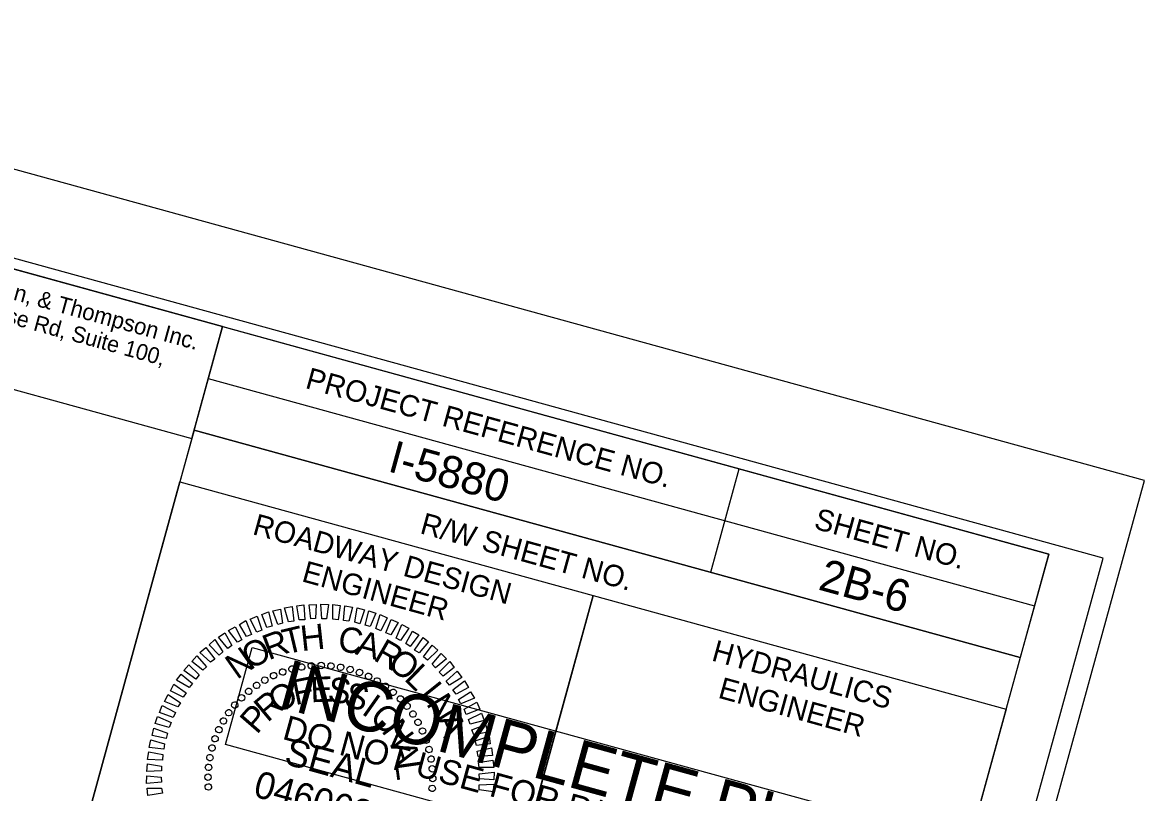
# Model space of a CAD drawing. Extents: x 1641192 to 2864602, y 841295 to 973236.
# Drawn here: x 1642843.9 to 1643105.8, y 842278.3 to 842457.9 of the extents above; entities that cross this region are included whole.
import ezdxf

# ---------------------------------------------------------------- set-up
doc = ezdxf.new("R2010")
doc.units = 0
for name, color, linetype in [('Old_Level_2', 7, 'Continuous'), ('Prop Dimension Text', 7, 'Continuous'), ('Sheet Data Field CELL', 7, 'Continuous'), ('Sheet Plan CELL', 7, 'Continuous'), ('Sheet Plot Border Inside CELL', 7, 'Continuous'), ('Sheet Plot Border Outside CELL', 7, 'Continuous'), ('Sheet Sticker Incomplete CELL', 7, 'Continuous')]:
    doc.layers.add(name, color=color, linetype=linetype)

msp = doc.modelspace()

# ---------------------------------------------------------------- linework, layer by layer
at = {"layer": 'Old_Level_2'}
for p, q in [((1642906.8, 842307.08), (1642906.8, 842307.08)), ((1642909.03, 842307.58), (1642909.03, 842307.58)), ((1642911.27, 842307.87), (1642911.27, 842307.87)), ((1642913.55, 842307.94), (1642913.55, 842307.94)), ((1642915.88, 842307.77), (1642915.88, 842307.77)), ((1642918.14, 842307.52), (1642918.14, 842307.52)), ((1642920.38, 842306.99), (1642920.38, 842306.99)), ((1642900.41, 842304.5), (1642900.41, 842304.5)), ((1642902.48, 842305.59), (1642902.48, 842305.59)), ((1642904.57, 842306.41), (1642904.57, 842306.41)), ((1642922.57, 842306.27), (1642922.57, 842306.27)), ((1642924.66, 842305.36), (1642924.66, 842305.36)), ((1642926.67, 842304.36), (1642926.67, 842304.36)), ((1642896.67, 842301.9), (1642896.67, 842301.9)), ((1642898.49, 842303.32), (1642898.49, 842303.32)), ((1642928.61, 842303.1), (1642928.61, 842303.1)), ((1642930.4, 842301.67), (1642930.4, 842301.67)), ((1642894.94, 842300.4), (1642894.94, 842300.4)), ((1642932.12, 842300.15), (1642932.12, 842300.15)), ((1642891.99, 842296.9), (1642891.99, 842296.9)), ((1642893.42, 842298.69), (1642893.42, 842298.69)), ((1642933.62, 842298.42), (1642933.62, 842298.42)), ((1642935.04, 842296.59), (1642935.04, 842296.59)), ((1642890.73, 842294.95), (1642890.73, 842294.95)), ((1642936.22, 842294.67), (1642936.22, 842294.67)), ((1642889.73, 842292.94), (1642889.73, 842292.94)), ((1642937.31, 842292.61), (1642937.31, 842292.61)), ((1642888.09, 842288.66), (1642888.09, 842288.66)), ((1642888.82, 842290.85), (1642888.82, 842290.85)), ((1642938.12, 842290.51), (1642938.12, 842290.51)), ((1642938.79, 842288.29), (1642938.79, 842288.29)), ((1642887.57, 842286.42), (1642887.57, 842286.42)), ((1642939.3, 842286.05), (1642939.3, 842286.05)), ((1642887.32, 842284.17), (1642887.32, 842284.17)), ((1642939.59, 842283.82), (1642939.59, 842283.82)), ((1642887.15, 842281.83), (1642887.15, 842281.83)), ((1642913.4, 842281.69), (1642913.4, 842281.69)), ((1642939.65, 842281.54), (1642939.65, 842281.54)), ((1642887.21, 842279.55), (1642887.21, 842279.55)), ((1642939.49, 842279.21), (1642939.49, 842279.21))]:
    msp.add_line(p, q, dxfattribs=at)
for points in [[(1642900.91, 842316.74), (1642899.7, 842319.8), (1642901.26, 842320.43), (1642902.18, 842317.06)], [(1642903.46, 842317.43), (1642902.29, 842320.65), (1642904.07, 842321.06), (1642904.58, 842317.79)], [(1642905.95, 842318.09), (1642905.06, 842321.34), (1642906.81, 842321.65), (1642907.18, 842318.26)], [(1642908.45, 842318.58), (1642907.89, 842321.86), (1642909.56, 842322.08), (1642909.8, 842318.56)], [(1642911.14, 842318.76), (1642910.76, 842322.09), (1642912.44, 842322.15), (1642912.3, 842318.84)], [(1642913.74, 842318.79), (1642913.5, 842322.25), (1642915.31, 842322.17), (1642914.87, 842318.77)], [(1642916.32, 842318.72), (1642916.34, 842322.17), (1642918.05, 842321.9), (1642917.57, 842318.56)], [(1642918.83, 842318.4), (1642919.1, 842321.79), (1642920.87, 842321.55), (1642920.08, 842318.24)], [(1642921.42, 842318.01), (1642922.01, 842321.37), (1642923.67, 842320.89), (1642922.63, 842317.65)], [(1642923.84, 842317.33), (1642924.69, 842320.63), (1642926.34, 842320.15), (1642925.04, 842316.97)], [(1642926.33, 842316.53), (1642927.38, 842319.77), (1642928.97, 842319.04), (1642927.5, 842316.02)], [(1642896.16, 842314.66), (1642894.51, 842317.46), (1642896.04, 842318.37), (1642897.31, 842315.12)], [(1642898.59, 842315.71), (1642897.04, 842318.7), (1642898.68, 842319.42), (1642899.72, 842316.12)], [(1642928.66, 842315.5), (1642929.95, 842318.63), (1642931.56, 842317.95), (1642929.84, 842315.04)], [(1642931.1, 842314.28), (1642932.45, 842317.45), (1642934.07, 842316.6), (1642932.1, 842313.76)], [(1642891.77, 842311.85), (1642889.65, 842314.5), (1642891.1, 842315.53), (1642892.72, 842312.58)], [(1642894.04, 842313.32), (1642891.99, 842316.06), (1642893.55, 842316.9), (1642895.06, 842313.92)], [(1642933.36, 842313), (1642934.93, 842315.95), (1642936.37, 842315.04), (1642934.34, 842312.37)], [(1642887.72, 842308.68), (1642885.27, 842310.92), (1642886.65, 842312.08), (1642888.76, 842309.38)], [(1642889.76, 842310.31), (1642887.47, 842312.74), (1642888.8, 842313.96), (1642890.66, 842311.11)], [(1642935.41, 842311.51), (1642937.39, 842314.4), (1642938.65, 842313.43), (1642936.48, 842310.85)], [(1642937.44, 842309.96), (1642939.47, 842312.62), (1642940.86, 842311.51), (1642938.41, 842309.12)], [(1642885.95, 842306.81), (1642883.38, 842308.82), (1642884.55, 842310.19), (1642886.8, 842307.62)], [(1642939.47, 842308.2), (1642941.58, 842310.73), (1642942.88, 842309.48), (1642940.28, 842307.34)], [(1642884.34, 842304.74), (1642881.49, 842306.71), (1642882.66, 842308.09), (1642885.13, 842305.73)], [(1642941.1, 842306.32), (1642943.62, 842308.8), (1642944.67, 842307.4), (1642942.06, 842305.43)], [(1642882.75, 842302.77), (1642879.84, 842304.49), (1642880.91, 842305.89), (1642883.58, 842303.69)], [(1642942.78, 842304.27), (1642945.37, 842306.57), (1642946.4, 842305.12), (1642943.56, 842303.31)], [(1642944.31, 842302.21), (1642947.06, 842304.31), (1642947.96, 842302.78), (1642945.07, 842301.2)], [(1642881.37, 842300.54), (1642878.4, 842302), (1642879.18, 842303.58), (1642882.05, 842301.5)], [(1642945.67, 842299.97), (1642948.46, 842301.79), (1642949.37, 842300.26), (1642946.23, 842298.96)], [(1642880.09, 842298.27), (1642877.05, 842299.48), (1642877.85, 842301.12), (1642880.76, 842299.23)], [(1642946.98, 842297.69), (1642949.89, 842299.37), (1642950.61, 842297.73), (1642947.43, 842296.49)], [(1642879.02, 842295.8), (1642875.85, 842296.93), (1642876.5, 842298.6), (1642879.58, 842296.95)], [(1642947.99, 842295.32), (1642951.02, 842296.81), (1642951.61, 842295.1), (1642948.35, 842294.2)], [(1642878.14, 842293.43), (1642874.87, 842294.37), (1642875.4, 842296.02), (1642878.55, 842294.62)], [(1642948.78, 842292.91), (1642951.95, 842294.14), (1642952.53, 842292.38), (1642949.23, 842291.71)], [(1642877.44, 842290.91), (1642874.11, 842291.6), (1642874.55, 842293.32), (1642877.75, 842292.12)], [(1642949.52, 842290.34), (1642952.81, 842291.39), (1642953.07, 842289.65), (1642949.88, 842289.22)], [(1642876.84, 842288.36), (1642873.45, 842288.8), (1642873.79, 842290.55), (1642877.05, 842289.61)], [(1642949.98, 842287.9), (1642953.35, 842288.66), (1642953.6, 842286.87), (1642950.2, 842286.66)], [(1642876.52, 842285.85), (1642873.05, 842285.99), (1642873.34, 842287.75), (1642876.63, 842287.12)], [(1642950.28, 842285.29), (1642953.7, 842285.81), (1642953.86, 842284.1), (1642950.51, 842284.1)], [(1642876.35, 842283.31), (1642872.92, 842283.16), (1642873.05, 842284.96), (1642876.32, 842284.45)], [(1642876.34, 842280.72), (1642872.8, 842280.39), (1642872.92, 842282.14), (1642876.26, 842281.87)], [(1642950.46, 842282.65), (1642954, 842282.98), (1642953.88, 842281.23), (1642950.55, 842281.5)], [(1642876.53, 842278.08), (1642873.1, 842277.56), (1642872.94, 842279.27), (1642876.29, 842279.27)], [(1642950.45, 842280.06), (1642953.89, 842280.21), (1642953.75, 842278.41), (1642950.48, 842278.92)]]:
    msp.add_lwpolyline(points, close=True, dxfattribs=at)
for centre, major_axis in [((1642904.6, 842306.39), (-0.253, 0.709)), ((1642906.78, 842307.06), (-0.19, 0.729)), ((1642909.02, 842307.54), (-0.126, 0.742)), ((1642911.29, 842307.83), (-0.061, 0.751)), ((1642913.58, 842307.91), (0.005, 0.753)), ((1642915.86, 842307.8), (0.071, 0.75)), ((1642918.13, 842307.48), (0.136, 0.741)), ((1642920.36, 842306.97), (0.2, 0.726)), ((1642922.54, 842306.27), (0.262, 0.706)), ((1642898.5, 842303.27), (-0.428, 0.62)), ((1642900.44, 842304.49), (-0.372, 0.655)), ((1642902.48, 842305.53), (-0.314, 0.685)), ((1642924.65, 842305.38), (0.323, 0.68)), ((1642926.67, 842304.31), (0.381, 0.65)), ((1642896.68, 842301.89), (-0.48, 0.58)), ((1642928.59, 842303.07), (0.436, 0.614)), ((1642930.4, 842301.66), (0.488, 0.574)), ((1642893.42, 842298.68), (-0.574, 0.488)), ((1642894.98, 842300.36), (-0.529, 0.536)), ((1642932.07, 842300.11), (0.536, 0.529)), ((1642933.61, 842298.41), (0.58, 0.48)), ((1642892.02, 842296.87), (-0.614, 0.436)), ((1642934.99, 842296.58), (0.62, 0.428)), ((1642889.71, 842292.93), (-0.68, 0.323)), ((1642890.78, 842294.95), (-0.65, 0.381)), ((1642936.2, 842294.65), (0.655, 0.372)), ((1642888.82, 842290.82), (-0.706, 0.262)), ((1642937.25, 842292.61), (0.685, 0.314)), ((1642938.11, 842290.49), (0.709, 0.253)), ((1642888.11, 842288.64), (-0.726, 0.2)), ((1642938.78, 842288.3), (0.729, 0.19)), ((1642887.6, 842286.41), (-0.741, 0.136)), ((1642939.26, 842286.07), (0.742, 0.126)), ((1642887.29, 842284.15), (-0.75, 0.071)), ((1642939.54, 842283.79), (0.751, 0.061)), ((1642887.17, 842281.86), (-0.753, 0.005)), ((1642939.63, 842281.51), (0.753, -0.005)), ((1642887.26, 842279.58), (-0.751, -0.061)), ((1642939.51, 842279.22), (0.75, -0.071))]:
    msp.add_ellipse(centre, major_axis=major_axis, ratio=0.999708, dxfattribs=at)
at = {"layer": 'Prop Dimension Text'}
msp.add_lwpolyline([(1642738.73, 842400.68), (1642883.38, 842360.88), (1642890.57, 842386.98), (1642745.92, 842426.79)], close=True, dxfattribs=at)
at = {"layer": 'Sheet Plan CELL'}
for p, q in [((1642887.23, 842374.88), (1643080.1, 842321.79)), ((1642883.91, 842362.79), (1642880.6, 842350.75)), ((1642883.91, 842362.79), (1643076.79, 842309.74)), ((1642883.91, 842362.79), (1643076.79, 842309.74)), ((1643011.08, 842353.74), (1643004.49, 842329.62)), ((1642977.06, 842324.21), (1642947.23, 842215.77))]:
    msp.add_line(p, q, dxfattribs=at)
for points in [[(1643083.47, 842333.88), (1641637.2, 842731.89), (1641358.6, 841719.52), (1642804.85, 841321.52)], [(1641358.6, 841719.52), (1641637.16, 842731.87), (1642890.57, 842386.98), (1642850.76, 842242.29), (1643043.63, 842189.2), (1642804.85, 841321.52)], [(1642890.57, 842386.98), (1643083.47, 842333.88), (1643076.79, 842309.74), (1642883.91, 842362.79)], [(1642880.6, 842350.75), (1642977.06, 842324.21), (1642947.21, 842215.73), (1642850.76, 842242.29)], [(1642977.06, 842324.21), (1643073.47, 842297.69), (1643043.63, 842189.2), (1642947.21, 842215.73)]]:
    msp.add_lwpolyline(points, close=True, dxfattribs=at)
at = {"layer": 'Sheet Plot Border Inside CELL'}
msp.add_lwpolyline([(1641209.95, 841757.82), (1642816.23, 841315.8), (1643096.16, 842332.97), (1641489.87, 842775.01)], close=True, dxfattribs=at)
at = {"layer": 'Sheet Plot Border Outside CELL'}
msp.add_lwpolyline([(1641192.11, 841741.99), (1642815.27, 841295.31), (1643105.8, 842351.06), (1641482.64, 842797.74)], close=True, dxfattribs=at)
msp.add_lwpolyline([(1641192.11, 841741.99), (1642815.27, 841295.31), (1643105.8, 842351.06), (1641482.64, 842797.74)], close=True, dxfattribs=at)
at = {"layer": 'Sheet Sticker Incomplete CELL'}
msp.add_lwpolyline([(1642891.27, 842289.47), (1642897.51, 842312.13), (1643039.24, 842273.13), (1643033, 842250.47)], close=True, dxfattribs=at)

# ---------------------------------------------------------------- texts
at = {"layer": 'Old_Level_2'}
for s, height, rotation, p in [('T', 5.9, 13.4333, (1642905.33, 842310.42)), ('H', 5.9, 6.233, (1642909.05, 842311.25)), ('R', 5.9, 20.634, (1642901.32, 842309.08)), ('C', 5.9, 351.8334, (1642917.27, 842311.3)), ('A', 5.9, 344.6338, (1642921.35, 842310.58)), ('N', 5.9, 35.037, (1642893.93, 842304.49)), ('O', 5.9, 27.8352, (1642897.02, 842306.83)), ('R', 5.9, 330.2346, (1642925.55, 842309.28)), ('O', 5.9, 323.0347, (1642928.75, 842307.65)), ('L', 5.9, 315.8344, (1642932.73, 842304.64)), ('F', 5.9, 11.5805, (1642907.54, 842298.63)), ('E', 5.9, 2.2246, (1642911.18, 842299.31)), ('S', 5.9, 352.8691, (1642914.94, 842299.48)), ('I', 5.9, 308.6336, (1642936.21, 842301.15)), ('R', 5.9, 39.6532, (1642901.03, 842294.47)), ('O', 5.9, 30.2947, (1642903.43, 842296.5)), ('S', 5.9, 343.5139, (1642918.6, 842298.6)), ('N', 5.9, 301.4324, (1642937.98, 842299.02)), ('I', 5.9, 324.8031, (1642922.78, 842296.77)), ('P', 5.9, 49.0124, (1642898.57, 842291.64)), ('O', 5.9, 315.447, (1642924.62, 842295.54)), ('N', 5.9, 306.0901, (1642927.49, 842292.65)), ('A', 5.9, 294.2307, (1642940.21, 842295.27)), ('SEAL', 6.273, 344.6135, (1642904.7, 842285)), ('A', 5.9, 287.3738, (1642929.71, 842289.27)), ('046062', 6.275, 344.6135, (1642897.46, 842277.44)), ('L', 5.9, 278.0144, (1642930.78, 842285.27))]:
    msp.add_text(s, height=height, rotation=rotation, dxfattribs=at).set_placement(p)
at = {"layer": 'Prop Dimension Text'}
for s, height, p in [('Johnson, Mirmiran, & Thompson Inc.', 3.8334, (1642803.65, 842403.71)), ('4700 Falls of Neuse Rd, Suite 100, ', 3.7239, (1642802.15, 842398.28))]:
    msp.add_text(s, height=height, rotation=344.6135, dxfattribs=at).set_placement(p)
at = {"layer": 'Sheet Data Field CELL'}
for s, p in [('I-5880', (1642928.87, 842353.28)), ('2B-6', (1643029.37, 842325.69))]:
    msp.add_text(s, height=7.5, rotation=344.6135, dxfattribs=at).set_placement(p)
at = {"layer": 'Sheet Plan CELL'}
for s, height, p in [('PROJECT REFERENCE NO.', 5.0001, (1642909.66, 842372.68)), ('R/W SHEET NO.', 5.0001, (1642936.43, 842338.81)), ('SHEET NO.', 5, (1643028.38, 842339.89)), ('ROADWAY DESIGN', 5.0001, (1642897.34, 842338.57)), ('ENGINEER', 5, (1642908.83, 842327.59)), ('HYDRAULICS', 5, (1643004.5, 842309.11)), ('ENGINEER', 5, (1643006.02, 842300.43))]:
    msp.add_text(s, height=height, rotation=344.6135, dxfattribs=at).set_placement(p)
at = {"layer": 'Sheet Sticker Incomplete CELL'}
for s, height, p in [('INCOMPLETE PLANS', 11.52, (1642903.01, 842298.38)), ('DO NOT USE FOR R/W ACQUISITION', 5.76, (1642904.29, 842290.82))]:
    msp.add_text(s, height=height, rotation=344.6135, dxfattribs=at).set_placement(p)

doc.saveas('drawing.dxf')
